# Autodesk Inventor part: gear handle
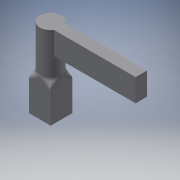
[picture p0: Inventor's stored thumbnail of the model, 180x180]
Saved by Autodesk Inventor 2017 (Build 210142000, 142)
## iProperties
Created: 2017-05
Part Number: gear handle
Material: Generic
Document SubType Name: Modeling
Designer: 1717440
Density: 1 g/cm^3
Appearance: Default
Author: 1717440
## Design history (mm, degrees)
sketch "Sketch1"
  geometry: L1 (-5.1, 5.1)-(5.1, 5.1) reference; L2 (-5.1, -5.1)-(-5.1, 5.1) reference; L3 (5.1, -5.1)-(-5.1, -5.1) reference; L4 (5.1, 5.1)-(5.1, -5.1) reference; L5 (4.8, -4.8)-(-4.8, -4.8); L6 (-4.8, -4.8)-(-4.8, 4.8); L7 (-4.8, 4.8)-(4.8, 4.8); L8 (4.8, 4.8)-(4.8, -4.8); 1 further point
  constraints: 8 end point, 3 other
  dimensions: "d0" = 0.3 distance between parallel lines of L4 L8
extrude "Extrusion1" new body sketch "Sketch1" distance "d1" = 15; taper "d2" = 0 deg
sketch "Sketch2"
  geometry: C1 r 4.7 at (0, 0); 1 further point
  constraints: 1 centre point, 1 coincident
  dimensions: "d3" = 9.4 diameter of C1
extrude "Extrusion2" join sketch "Sketch2" distance "d4" = 20; taper "d5" = 0 deg
fillet "Fillet1" dims "d6" = 2
sketch "Sketch3"
  geometry: L1 (0, 0)-(40, 0); L2 (40, 0)-(40, -2.5); L3 (40, -2.5)-(0, -2.5); L4 (40, 0)-(40, 2.5); L5 (40, 2.5)-(0, 2.5); L6 (0, 2.5)-(0, -2.5); C1 r 4.7 at (0, 0) reference
  constraints: 12 end point, 2 symmetric about line, 2 vertical, 1 horizontal, 1 perpendicular
  dimensions: "d7" = 40 distance of L1.start L1.end; "d8" = 2.5 distance of L1.end L2.end
extrude "Extrusion3" join sketch "Sketch3" distance "d9" = 10; taper "d10" = 0 deg
fillet "Fillet2" dims "d11" = 3
fillet "Fillet3" dims "d12" = 2
fillet "Fillet4" dims "d13" = 2
body "Solid1"
node "Reference1"
